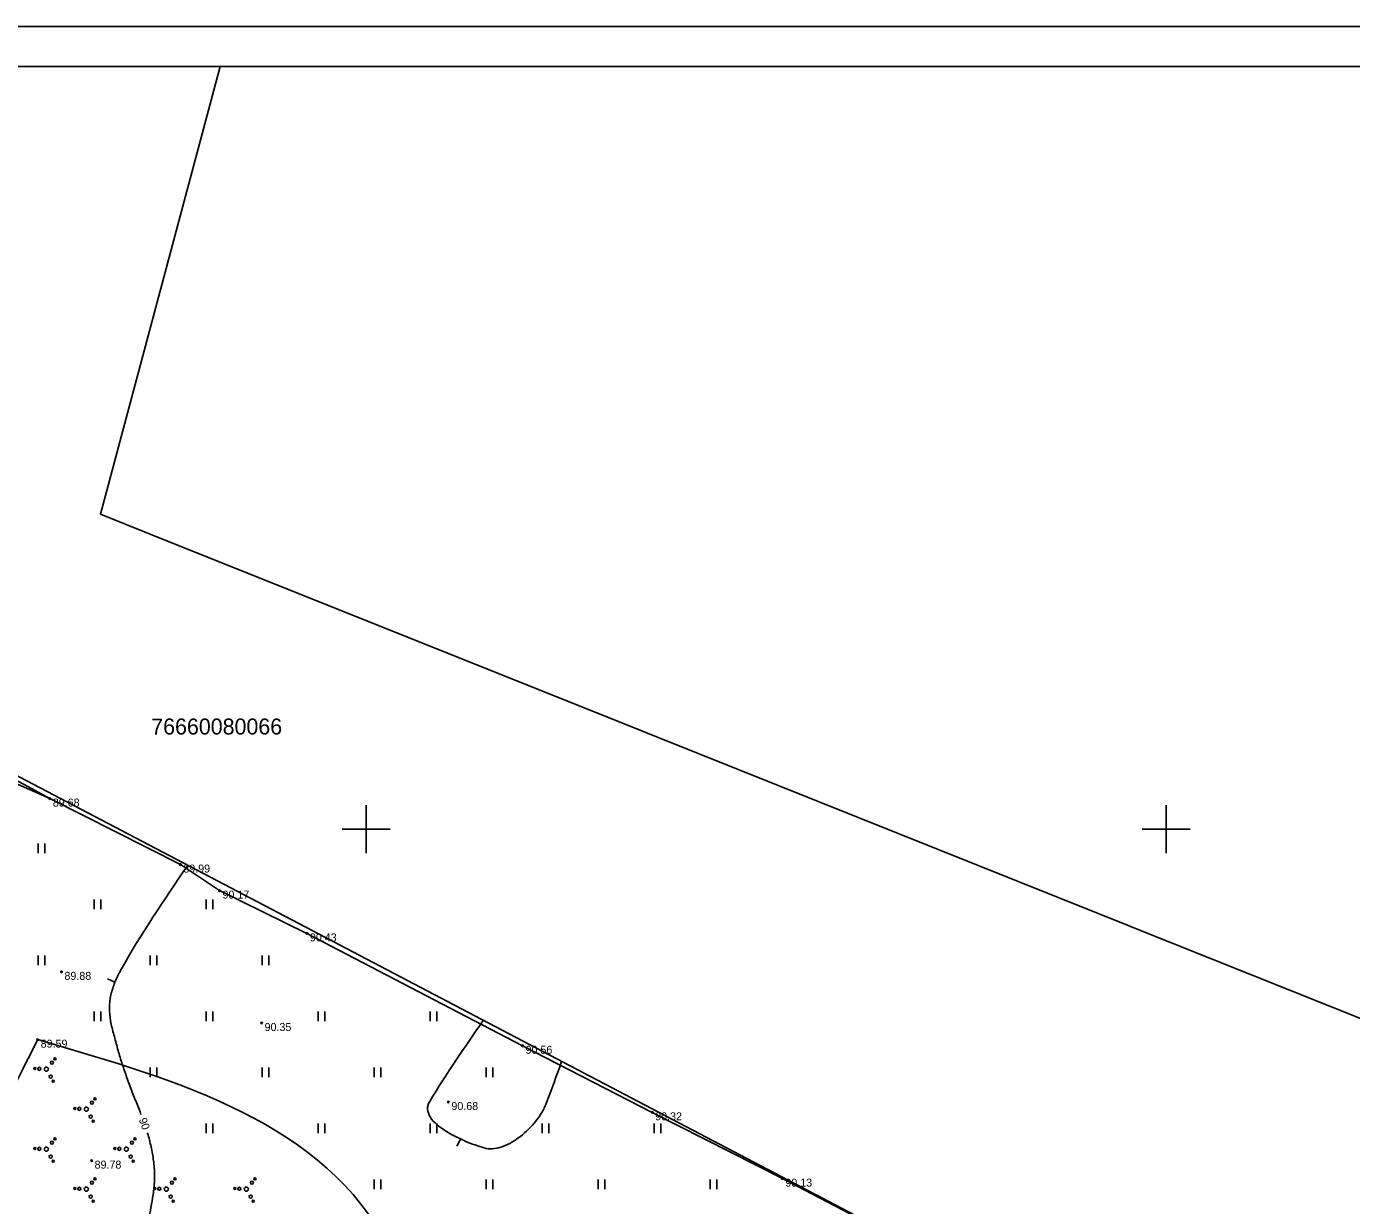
# Model space of a CAD drawing. Extents: x 635228 to 635525, y 248590 to 248800.
# Drawn here: x 635378.8 to 635461.6, y 248726.5 to 248800.2 of the extents above; entities that cross this region are included whole.
import ezdxf

# ---------------------------------------------------------------- set-up
doc = ezdxf.new("R2010")
doc.units = 0
for name, color, linetype in [('GEOD_ELEM_####_####_#', 7, 'Continuous'), ('NORB_ZOGS_ZSTP_####_#', 7, 'Continuous'), ('RAMI_PLAN_####_TKST_#', 7, 'Continuous'), ('RAMI_UZMR_####_####_#', 7, 'Continuous'), ('RELJ_AATZ_####_TKST_#', 7, 'Continuous'), ('RELJ_ELEM_####_####_#', 7, 'Continuous'), ('RELJ_HORZ_####_TKST_#', 7, 'Continuous'), ('RELJ_HORZ_PAMT_####_#', 7, 'Continuous'), ('RELJ_HORZ_RESN_####_#', 7, 'Continuous'), ('ROBZ_IERR_####_####_#', 7, 'Continuous'), ('ROBZ_IERR_####_TKST_#', 7, 'Continuous'), ('ROBZ_UZMR_####_####_#', 7, 'Continuous'), ('TERT_ELEM_####_####_#', 7, 'Continuous'), ('TERT_KONT_####_####_#', 7, 'Continuous')]:
    doc.layers.add(name, color=color, linetype=linetype)

msp = doc.modelspace()

# ---------------------------------------------------------------- linework, layer by layer
at = {"layer": 'GEOD_ELEM_####_####_#'}
for p, q in [((635400, 248751.5), (635400, 248750)), ((635450, 248751.5), (635450, 248750)), ((635398.5, 248750), (635400, 248750)), ((635400, 248750), (635400, 248748.5)), ((635400, 248750), (635401.5, 248750)), ((635448.5, 248750), (635450, 248750)), ((635450, 248750), (635450, 248748.5)), ((635450, 248750), (635451.5, 248750))]:
    msp.add_line(p, q, dxfattribs=at)
at = {"layer": 'NORB_ZOGS_ZSTP_####_#'}
msp.add_lwpolyline([(635360.648, 248762.312), (635368.914, 248758.068), (635380.222, 248751.913), (635388.377, 248747.789), (635390.826, 248746.16), (635396.286, 248743.485), (635409.766, 248736.46), (635417.87, 248732.3), (635426.003, 248728.155), (635436.69, 248722.584), (635450.108, 248715.457), (635458.287, 248711.346), (635460.113, 248714.625)], dxfattribs=at)
at = {"layer": 'RAMI_PLAN_####_TKST_#'}
for points in [[(635227.837, 248590.176), (635227.837, 248800.176), (635524.837, 248800.176), (635524.837, 248590.176)], [(635237.837, 248797.676), (635237.837, 248592.676), (635522.337, 248592.676), (635522.337, 248797.676)]]:
    msp.add_lwpolyline(points, close=True, dxfattribs=at)
at = {"layer": 'RAMI_UZMR_####_####_#'}
msp.add_lwpolyline([(635376.384, 248753.612), (635380.222, 248751.913), (635388.377, 248747.789), (635390.826, 248746.16), (635396.286, 248743.485), (635409.766, 248736.46), (635417.87, 248732.3), (635426.003, 248728.155), (635436.69, 248722.584)], dxfattribs=at)
at = {"layer": 'RELJ_ELEM_####_####_#'}
for centre in [(635380.222, 248751.913), (635388.377, 248747.789), (635390.826, 248746.16), (635396.286, 248743.485), (635380.948, 248741.082), (635393.457, 248737.884), (635379.461, 248736.844), (635409.766, 248736.46), (635405.132, 248732.946), (635417.87, 248732.3), (635382.832, 248729.283), (635426.003, 248728.155)]:
    msp.add_circle(centre, 0.05, dxfattribs=at)
at = {"layer": 'RELJ_HORZ_PAMT_####_#'}
msp.add_line((635405.894, 248730.63), (635405.656, 248730.19), dxfattribs=at)
msp.add_spline([(635407.304, 248738.05), (635403.964, 248732.977), (635403.897, 248732.857), (635403.852, 248732.737), (635403.825, 248732.496), (635403.991, 248732.02), (635404.959, 248731.139), (635406.313, 248730.445), (635406.959, 248730.203), (635407.245, 248730.113), (635407.374, 248730.078), (635407.493, 248730.048), (635408.524, 248730.159), (635409.627, 248730.793), (635410.6, 248731.755), (635410.973, 248732.298), (635411.121, 248732.574), (635411.238, 248732.85), (635412.206, 248735.478)], degree=3, dxfattribs=at)
at = {"layer": 'RELJ_HORZ_RESN_####_#'}
msp.add_line((635384.281, 248740.433), (635383.824, 248740.636), dxfattribs=at)
for points in [[(635385.917, 248732.174), (635385.673, 248732.802), (635385.326, 248733.679), (635384.999, 248734.573), (635384.714, 248735.422), (635384.458, 248736.277), (635384.226, 248737.144), (635384.016, 248738.026), (635383.947, 248738.822), (635384.038, 248739.641), (635384.148, 248740.042), (635384.28, 248740.431), (635384.641, 248741.159), (635388.837, 248747.739)], [(635370.286, 248702.191), (635371.268, 248702.893), (635371.931, 248703.448), (635372.235, 248703.758), (635372.523, 248704.086), (635373.233, 248705.103), (635373.842, 248706.207), (635374.44, 248707.318), (635375.119, 248708.351), (635375.519, 248708.837), (635375.945, 248709.297), (635376.871, 248710.138), (635378.872, 248711.708), (635380.875, 248713.355), (635381.799, 248714.3), (635382.631, 248715.376), (635384.271, 248718.308), (635385.412, 248721.331), (635386.184, 248724.417), (635386.472, 248725.973), (635386.718, 248727.534), (635386.765, 248728.402), (635386.702, 248729.274), (635386.549, 248730.144), (635386.323, 248731.007), (635386.319, 248731.019)]]:
    msp.add_spline(points, degree=3, dxfattribs=at)
at = {"layer": 'ROBZ_IERR_####_####_#'}
msp.add_lwpolyline([(635390.87, 248797.676), (635383.387, 248769.687), (635386.484, 248768.447), (635478.377, 248731.658), (635482.561, 248729.828), (635465.459, 248707.539), (635458.607, 248711.134), (635360.483, 248762.615), (635360.888, 248769.918), (635363.321, 248797.676)], dxfattribs=at)
at = {"layer": 'ROBZ_UZMR_####_####_#'}
msp.add_lwpolyline([(635325.542, 248659.74), (635329.653, 248676.366), (635327.79, 248676.828), (635337.46, 248688.66), (635343.343, 248703.12), (635360.483, 248762.615), (635458.607, 248711.134), (635465.459, 248707.539), (635439.457, 248681.038), (635424.543, 248670.014), (635420.979, 248667.379), (635407.07, 248653.18), (635400.067, 248641.149), (635395.162, 248617.539), (635389.031, 248621.062), (635375.858, 248629.115)], close=True, dxfattribs=at)
at = {"layer": 'TERT_ELEM_####_####_#'}
for p, q in [((635379.5, 248748.5), (635379.5, 248749.1)), ((635379.9, 248748.5), (635379.9, 248749.1)), ((635383, 248745), (635383, 248745.6)), ((635383.4, 248745), (635383.4, 248745.6)), ((635390, 248745), (635390, 248745.6)), ((635390.4, 248745), (635390.4, 248745.6)), ((635379.5, 248741.5), (635379.5, 248742.1)), ((635379.9, 248741.5), (635379.9, 248742.1)), ((635386.5, 248741.5), (635386.5, 248742.1)), ((635386.9, 248741.5), (635386.9, 248742.1)), ((635393.5, 248741.5), (635393.5, 248742.1)), ((635393.9, 248741.5), (635393.9, 248742.1)), ((635383, 248738), (635383, 248738.6)), ((635383.4, 248738), (635383.4, 248738.6)), ((635390, 248738), (635390, 248738.6)), ((635390.4, 248738), (635390.4, 248738.6)), ((635397, 248738), (635397, 248738.6)), ((635397.4, 248738), (635397.4, 248738.6)), ((635404, 248738), (635404, 248738.6)), ((635404.4, 248738), (635404.4, 248738.6)), ((635386.5, 248734.5), (635386.5, 248735.1)), ((635386.9, 248734.5), (635386.9, 248735.1)), ((635393.5, 248734.5), (635393.5, 248735.1)), ((635393.9, 248734.5), (635393.9, 248735.1)), ((635400.5, 248734.5), (635400.5, 248735.1)), ((635400.9, 248734.5), (635400.9, 248735.1)), ((635407.5, 248734.5), (635407.5, 248735.1)), ((635407.9, 248734.5), (635407.9, 248735.1)), ((635390, 248731), (635390, 248731.6)), ((635390.4, 248731), (635390.4, 248731.6)), ((635397, 248731), (635397, 248731.6)), ((635397.4, 248731), (635397.4, 248731.6)), ((635404, 248731), (635404, 248731.6)), ((635404.4, 248731), (635404.4, 248731.6)), ((635411, 248731), (635411, 248731.6)), ((635411.4, 248731), (635411.4, 248731.6)), ((635418, 248731), (635418, 248731.6)), ((635418.4, 248731), (635418.4, 248731.6)), ((635400.5, 248727.5), (635400.5, 248728.1)), ((635400.9, 248727.5), (635400.9, 248728.1)), ((635407.5, 248727.5), (635407.5, 248728.1)), ((635407.9, 248727.5), (635407.9, 248728.1)), ((635414.5, 248727.5), (635414.5, 248728.1)), ((635414.9, 248727.5), (635414.9, 248728.1)), ((635421.5, 248727.5), (635421.5, 248728.1)), ((635421.9, 248727.5), (635421.9, 248728.1))]:
    msp.add_line(p, q, dxfattribs=at)
for centre, radius in [((635380, 248735), 0.128), ((635380.348, 248735.408), 0.096), ((635380.544, 248735.639), 0.064), ((635379.282, 248735.034), 0.064), ((635379.566, 248735.021), 0.096), ((635380.276, 248734.533), 0.096), ((635380.434, 248734.244), 0.064), ((635382.848, 248732.908), 0.096), ((635383.044, 248733.139), 0.064), ((635381.782, 248732.534), 0.064), ((635382.066, 248732.521), 0.096), ((635382.5, 248732.5), 0.128), ((635382.776, 248732.033), 0.096), ((635382.934, 248731.744), 0.064), ((635380.348, 248730.408), 0.096), ((635380.544, 248730.639), 0.064), ((635385.348, 248730.408), 0.096), ((635385.544, 248730.639), 0.064), ((635379.282, 248730.034), 0.064), ((635379.566, 248730.021), 0.096), ((635380, 248730), 0.128), ((635380.276, 248729.533), 0.096), ((635384.282, 248730.034), 0.064), ((635384.566, 248730.021), 0.096), ((635385, 248730), 0.128), ((635385.276, 248729.533), 0.096), ((635380.434, 248729.244), 0.064), ((635385.434, 248729.244), 0.064), ((635382.848, 248727.908), 0.096), ((635383.044, 248728.139), 0.064), ((635387.848, 248727.908), 0.096), ((635388.044, 248728.139), 0.064), ((635392.848, 248727.908), 0.096), ((635393.044, 248728.139), 0.064), ((635381.782, 248727.534), 0.064), ((635382.066, 248727.521), 0.096), ((635382.5, 248727.5), 0.128), ((635382.776, 248727.033), 0.096), ((635386.782, 248727.534), 0.064), ((635387.066, 248727.521), 0.096), ((635387.5, 248727.5), 0.128), ((635387.776, 248727.033), 0.096), ((635391.782, 248727.534), 0.064), ((635392.066, 248727.521), 0.096), ((635392.5, 248727.5), 0.128), ((635392.776, 248727.033), 0.096), ((635382.934, 248726.744), 0.064), ((635387.934, 248726.744), 0.064), ((635392.934, 248726.744), 0.064)]:
    msp.add_circle(centre, radius, dxfattribs=at)
at = {"layer": 'TERT_KONT_####_####_#'}
for points in [[(635379.461, 248736.844), (635375.752, 248729.243), (635374.224, 248724.864), (635373.958, 248720.932), (635373.4, 248711.674)], [(635386.085, 248703.415), (635403.077, 248714.603), (635401.393, 248723.874), (635379.461, 248736.844)]]:
    msp.add_spline(points, degree=3, dxfattribs=at)

# ---------------------------------------------------------------- texts
at = {"layer": 'RELJ_AATZ_####_TKST_#'}
for s, p in [(' 89.68', (635380.222, 248751.413)), (' 89.99', (635388.377, 248747.289)), (' 90.17', (635390.826, 248745.66)), (' 90.43', (635396.286, 248742.985)), (' 89.88', (635380.948, 248740.582)), (' 90.35', (635393.457, 248737.384)), (' 89.59', (635379.461, 248736.344)), (' 90.56', (635409.766, 248735.96)), (' 90.68', (635405.132, 248732.446)), (' 90.32', (635417.87, 248731.8)), (' 89.78', (635382.832, 248728.783)), (' 90.13', (635426.003, 248727.655))]:
    msp.add_text(s, height=0.5, dxfattribs=at).set_placement(p)
at = {"layer": 'RELJ_HORZ_####_TKST_#'}
msp.add_text('90', height=0.5, rotation=289.26203, dxfattribs=at).set_placement((635385.776, 248731.86))
at = {"layer": 'ROBZ_IERR_####_TKST_#'}
msp.add_text('76660080066', height=1, dxfattribs=at).set_placement((635386.558, 248755.918))

doc.saveas('drawing.dxf')
